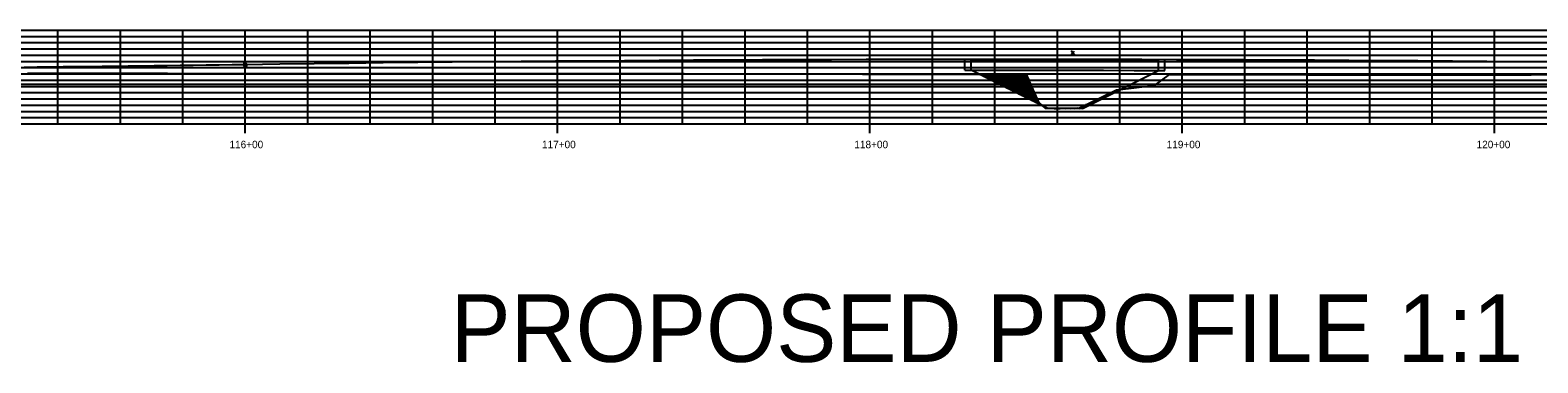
# Model space of a CAD drawing. Extents: x 1676565 to 1681112, y 227357 to 229815.
# Drawn here: x 1679698.4 to 1680181.1, y 229512.3 to 229618.8 of the extents above; entities that cross this region are included whole.
import ezdxf

# ---------------------------------------------------------------- set-up
doc = ezdxf.new("R2010")
doc.units = 0
for name, color, linetype in [('Default', 7, 'Continuous'), ('R_Axis', 7, 'Continuous'), ('R_Axis Annot', 7, 'Continuous'), ('R_Exist Surface', 7, 'Continuous'), ('R_Grid', 7, 'Continuous'), ('R_Point Sym', 7, 'Continuous'), ('R_Water', 7, 'Continuous'), ('S_BRIDGE', 7, 'Continuous')]:
    doc.layers.add(name, color=color, linetype=linetype)

msp = doc.modelspace()

# ---------------------------------------------------------------- linework, layer by layer
at = {"layer": 'Default'}
for points in [[(1679767.31, 229607.87), (1679778.35, 229608.02), (1679789.39, 229608.16), (1679800.43, 229608.3), (1679811.47, 229608.43), (1679822.52, 229608.55), (1679833.56, 229608.67), (1679844.6, 229608.78), (1679855.64, 229608.88), (1679866.68, 229608.98), (1679877.72, 229609.06), (1679888.77, 229609.14), (1679899.81, 229609.22), (1679910.85, 229609.29), (1679921.89, 229609.35), (1679932.93, 229609.4), (1679943.97, 229609.44), (1679955.02, 229609.48), (1679966.06, 229609.51), (1679977.1, 229609.54), (1679988.14, 229609.56), (1679999.18, 229609.57), (1680010.22, 229609.57), (1680021.27, 229609.57), (1680043.35, 229609.54), (1680054.39, 229609.52), (1680065.43, 229609.49), (1680076.47, 229609.45), (1680087.52, 229609.4), (1680098.56, 229609.35), (1680109.6, 229609.29), (1680120.64, 229609.22), (1680131.68, 229609.15), (1680142.72, 229609.07), (1680153.77, 229608.98), (1680164.81, 229608.89), (1680175.85, 229608.79), (1680186.89, 229608.68)], [(1679696.47, 229607.03), (1679700.64, 229607.07), (1679704.81, 229607.12), (1679708.97, 229607.16), (1679713.14, 229607.2), (1679717.31, 229607.25), (1679721.47, 229607.29), (1679725.64, 229607.34), (1679729.81, 229607.39), (1679733.97, 229607.44), (1679738.14, 229607.49), (1679742.31, 229607.54), (1679746.47, 229607.59), (1679750.64, 229607.64), (1679754.81, 229607.7), (1679758.97, 229607.75), (1679763.14, 229607.81), (1679767.31, 229607.87)]]:
    msp.add_lwpolyline(points, dxfattribs=at)
at = {"layer": 'R_Axis'}
msp.add_line((1678167.31, 229588.83), (1681067.31, 229588.83), dxfattribs=at)
at = {"layer": 'R_Exist Surface'}
msp.add_lwpolyline([(1679697.58, 229605.04), (1679705.05, 229605.05), (1679709.81, 229605.05), (1679710.23, 229605.05), (1679710.73, 229605.05), (1679712.52, 229605.05), (1679719.99, 229605.04), (1679727.46, 229605.03), (1679728.8, 229605.03), (1679729.01, 229605.03), (1679734.93, 229605.02), (1679738.16, 229605.01), (1679738.47, 229605.01), (1679742.4, 229605.01), (1679749.87, 229604.99), (1679752.24, 229604.99), (1679755.92, 229604.98), (1679757.34, 229604.98), (1679764.81, 229604.97), (1679769.24, 229604.96), (1679769.59, 229604.96), (1679772.28, 229604.96), (1679779.75, 229604.96), (1679780.84, 229604.95), (1679781.2, 229604.95), (1679787.22, 229604.96), (1679794.69, 229604.96), (1679802.16, 229604.95), (1679803.13, 229604.95), (1679804.09, 229604.95), (1679805.08, 229604.95), (1679809.63, 229604.96), (1679817.1, 229604.97), (1679821.74, 229604.97), (1679822.84, 229604.97), (1679824.57, 229604.97), (1679832.04, 229604.98), (1679839.39, 229604.99), (1679839.51, 229604.99), (1679840.27, 229604.99), (1679846.98, 229604.99), (1679854.45, 229605), (1679857.04, 229605), (1679857.45, 229605), (1679861.92, 229605), (1679869.39, 229605), (1679873.92, 229605), (1679874.09, 229605), (1679890.33, 229604.98), (1679890.91, 229604.97), (1679890.91, 229604.97), (1679907.68, 229604.94), (1679907.84, 229604.94), (1679926.35, 229604.87), (1679926.86, 229604.87), (1679945.1, 229604.8), (1679945.88, 229604.8), (1679946.66, 229604.8), (1679964.89, 229604.75), (1679965.52, 229604.75), (1679977.98, 229604.74), (1679978.62, 229604.74), (1679991.07, 229604.73), (1680003.48, 229604.72), (1680004.18, 229604.72), (1680016.57, 229604.71), (1680017.28, 229604.71), (1680019.42, 229599.87), (1680021.34, 229595.61), (1680021.67, 229595.37), (1680023.43, 229593.84), (1680026.28, 229593.79), (1680028.2, 229593.74), (1680031.87, 229593.9), (1680034.37, 229594.01), (1680045.81, 229599.51), (1680046.22, 229599.68), (1680046.6, 229599.74), (1680058.68, 229601.24), (1680058.73, 229601.28), (1680063.26, 229604.65), (1680063.41, 229604.66), (1680077.81, 229604.63), (1680092.11, 229604.6), (1680092.63, 229604.6), (1680106.92, 229604.57), (1680107.52, 229604.58), (1680121.79, 229604.55), (1680135.77, 229604.56), (1680136.09, 229604.56), (1680150.14, 229604.56), (1680150.39, 229604.56), (1680164.52, 229604.57), (1680164.68, 229604.57), (1680178.89, 229604.58), (1680178.98, 229604.58), (1680190.32, 229604.59)], dxfattribs=at)
at = {"layer": 'R_Grid'}
for p, q in [((1678167.31, 229618.83), (1681067.31, 229618.83)), ((1678167.31, 229618.83), (1681067.31, 229618.83)), ((1679707.31, 229588.83), (1679707.31, 229618.83)), ((1679727.31, 229588.83), (1679727.31, 229618.83)), ((1679747.31, 229588.83), (1679747.31, 229618.83)), ((1679767.31, 229588.83), (1679767.31, 229618.83)), ((1679787.31, 229588.83), (1679787.31, 229618.83)), ((1679807.31, 229588.83), (1679807.31, 229618.83)), ((1679827.31, 229588.83), (1679827.31, 229618.83)), ((1679847.31, 229588.83), (1679847.31, 229618.83)), ((1679867.31, 229588.83), (1679867.31, 229618.83)), ((1679887.31, 229588.83), (1679887.31, 229618.83)), ((1679907.31, 229588.83), (1679907.31, 229618.83)), ((1679927.31, 229588.83), (1679927.31, 229618.83)), ((1679947.31, 229588.83), (1679947.31, 229618.83)), ((1679967.31, 229588.83), (1679967.31, 229618.83)), ((1679987.31, 229588.83), (1679987.31, 229618.83)), ((1680007.31, 229588.83), (1680007.31, 229618.83)), ((1680027.31, 229588.83), (1680027.31, 229618.83)), ((1680047.31, 229588.83), (1680047.31, 229618.83)), ((1680067.31, 229588.83), (1680067.31, 229618.83)), ((1680087.31, 229588.83), (1680087.31, 229618.83)), ((1680107.31, 229588.83), (1680107.31, 229618.83)), ((1680127.31, 229588.83), (1680127.31, 229618.83)), ((1680147.31, 229588.83), (1680147.31, 229618.83)), ((1680167.31, 229588.83), (1680167.31, 229618.83)), ((1678167.31, 229616.83), (1681067.31, 229616.83)), ((1678167.31, 229614.83), (1681067.31, 229614.83)), ((1678167.31, 229612.83), (1681067.31, 229612.83)), ((1678167.31, 229610.83), (1681067.31, 229610.83)), ((1678167.31, 229608.83), (1681067.31, 229608.83)), ((1678167.31, 229606.83), (1681067.31, 229606.83)), ((1678167.31, 229604.83), (1681067.31, 229604.83)), ((1678167.31, 229602.83), (1681067.31, 229602.83)), ((1678167.31, 229600.83), (1681067.31, 229600.83)), ((1678167.31, 229598.83), (1681067.31, 229598.83)), ((1678167.31, 229596.83), (1681067.31, 229596.83)), ((1678167.31, 229594.83), (1681067.31, 229594.83)), ((1678167.31, 229592.83), (1681067.31, 229592.83)), ((1678167.31, 229590.83), (1681067.31, 229590.83)), ((1679767.31, 229585.83), (1679767.31, 229588.83)), ((1679867.31, 229585.83), (1679867.31, 229588.83)), ((1679967.31, 229585.83), (1679967.31, 229588.83)), ((1680067.31, 229585.83), (1680067.31, 229588.83)), ((1680167.31, 229585.83), (1680167.31, 229588.83))]:
    msp.add_line(p, q, dxfattribs=at)
at = {"layer": 'R_Point Sym'}
for points in [[(1680032.31, 229611.58), (1680031.81, 229612.08), (1680032.31, 229611.58), (1680031.81, 229611.08), (1680032.31, 229611.58), (1680032.81, 229611.08), (1680032.31, 229611.58), (1680032.81, 229612.08)], [(1679767.31, 229607.87), (1679766.81, 229608.37), (1679767.31, 229607.87), (1679766.81, 229607.37), (1679767.31, 229607.87), (1679767.81, 229607.37), (1679767.31, 229607.87), (1679767.81, 229608.37)]]:
    msp.add_lwpolyline(points, dxfattribs=at)
at = {"layer": 'R_Water'}
msp.add_line((1681080.69, 229601.46), (1678154.35, 229601.46), dxfattribs=at)
at = {"layer": 'S_BRIDGE'}
for p, q in [((1679997.72, 229606.02), (1679997.72, 229609.77)), ((1679999.72, 229606.02), (1679999.72, 229609.77)), ((1680059.72, 229605.94), (1680059.72, 229609.69)), ((1680061.72, 229605.93), (1680061.72, 229609.68)), ((1680024.28, 229593.74), (1679999.72, 229606.02)), ((1680002.53, 229604.61), (1680002.97, 229604.72)), ((1680003.01, 229604.38), (1680004.39, 229604.72)), ((1680003.48, 229604.14), (1680005.8, 229604.72)), ((1680003.95, 229603.9), (1680007.21, 229604.72)), ((1680004.42, 229603.67), (1680008.62, 229604.72)), ((1680004.89, 229603.43), (1680010.03, 229604.72)), ((1680005.36, 229603.2), (1680011.44, 229604.72)), ((1680005.83, 229602.96), (1680012.84, 229604.71)), ((1680006.31, 229602.73), (1680014.25, 229604.71)), ((1680006.78, 229602.49), (1680015.66, 229604.71)), ((1680007.25, 229602.25), (1680017.08, 229604.71)), ((1680007.72, 229602.02), (1680017.4, 229604.44)), ((1680008.19, 229601.78), (1680017.54, 229604.12)), ((1680008.66, 229601.55), (1680017.69, 229603.8)), ((1680035.32, 229593.74), (1680059.72, 229605.94)), ((1680009.13, 229601.31), (1680017.83, 229603.48)), ((1680009.61, 229601.08), (1680017.97, 229603.17)), ((1680010.08, 229600.84), (1680018.11, 229602.85)), ((1680010.55, 229600.6), (1680018.25, 229602.53)), ((1680011.02, 229600.37), (1680018.39, 229602.21)), ((1680011.49, 229600.13), (1680018.53, 229601.89)), ((1680011.96, 229599.9), (1680018.67, 229601.57)), ((1680012.43, 229599.66), (1680018.81, 229601.25)), ((1680012.91, 229599.43), (1680018.95, 229600.94)), ((1680013.38, 229599.19), (1680019.09, 229600.62)), ((1680013.85, 229598.95), (1680019.23, 229600.3)), ((1680014.32, 229598.72), (1680019.37, 229599.98)), ((1680014.79, 229598.48), (1680019.51, 229599.66)), ((1680015.26, 229598.25), (1680019.65, 229599.35)), ((1680015.73, 229598.01), (1680019.8, 229599.03)), ((1680044.04, 229598.66), (1680046.3, 229599.23)), ((1680045.57, 229599.4), (1680047.71, 229599.93)), ((1680016.21, 229597.78), (1680019.94, 229598.71)), ((1680016.68, 229597.54), (1680020.08, 229598.39)), ((1680017.15, 229597.3), (1680020.23, 229598.07)), ((1680017.62, 229597.07), (1680020.37, 229597.76)), ((1680018.09, 229596.83), (1680020.51, 229597.44)), ((1680018.56, 229596.6), (1680020.66, 229597.12)), ((1680019.03, 229596.36), (1680020.8, 229596.8)), ((1680019.51, 229596.13), (1680020.94, 229596.49)), ((1680019.98, 229595.89), (1680021.09, 229596.17)), ((1680020.45, 229595.65), (1680021.23, 229595.85)), ((1680020.92, 229595.42), (1680021.43, 229595.55)), ((1680021.39, 229595.18), (1680021.78, 229595.28)), ((1680021.86, 229594.95), (1680022.09, 229595.01)), ((1680022.33, 229594.71), (1680022.41, 229594.73)), ((1680034.24, 229593.74), (1680036.4, 229594.28)), ((1680034.87, 229594.25), (1680037.81, 229594.98)), ((1680036.4, 229594.99), (1680039.23, 229595.69)), ((1680037.93, 229595.72), (1680040.64, 229596.4)), ((1680039.46, 229596.46), (1680042.06, 229597.11)), ((1680040.98, 229597.19), (1680043.47, 229597.81)), ((1680042.51, 229597.93), (1680044.88, 229598.52)), ((1680035.32, 229593.74), (1680024.28, 229593.74)), ((1680035.28, 229593.74), (1680024.32, 229593.74)), ((1680028.59, 229593.74), (1680028.67, 229593.76)), ((1680030, 229593.74), (1680030.4, 229593.84)), ((1680031.41, 229593.74), (1680032.12, 229593.91)), ((1680032.83, 229593.74), (1680033.8, 229593.98))]:
    msp.add_line(p, q, dxfattribs=at)
for points in [[(1679999.72, 229609.02), (1680002.93, 229609.02), (1680012.72, 229609.02), (1680022.51, 229609.02), (1680042.1, 229608.99), (1680051.89, 229608.96), (1680059.72, 229608.94)], [(1679997.72, 229606.02), (1680012.72, 229606.02), (1680022.51, 229606.02), (1680042.09, 229605.99), (1680051.88, 229605.96), (1680061.72, 229605.93)]]:
    msp.add_lwpolyline(points, dxfattribs=at)

# ---------------------------------------------------------------- texts
at = {"layer": 'Default'}
msp.add_text('PROPOSED PROFILE 1:1', height=21.5917, dxfattribs=at).set_placement((1679833, 229512.65))
at = {"layer": 'R_Axis Annot'}
for s, p in [('116+00', (1679762.25, 229581.03)), ('117+00', (1679862.31, 229581.03)), ('118+00', (1679962.31, 229581.03)), ('119+00', (1680062.31, 229581.03)), ('120+00', (1680161.53, 229581.03))]:
    msp.add_text(s, height=2.4, dxfattribs=at).set_placement(p)

doc.saveas('drawing.dxf')
